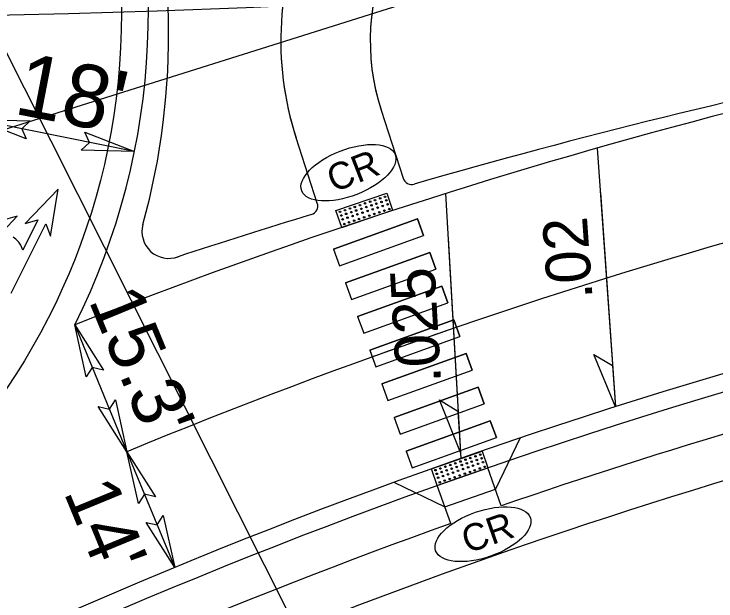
# Model space of a CAD drawing. Extents: x 2010838 to 2015151, y 441905 to 447792.
# Drawn here: x 2013251.3 to 2013329.7, y 444852.7 to 444918.3 of the extents above; entities that cross this region are included whole.
import ezdxf

# ---------------------------------------------------------------- set-up
doc = ezdxf.new("R2010")
doc.units = 0
for name, color, linetype in [('A-Wall-Abov', 7, 'Continuous'), ('A-Wall-Blow', 7, 'Continuous'), ('A-Wall-Comp', 7, 'Continuous'), ('C-CURB STOPS', 7, 'Continuous'), ('C-Grave Plots', 7, 'Continuous'), ('CLRD', 7, 'Continuous'), ('Default_10ft_LIDAR_Contou', 7, 'Continuous'), ('HATCH', 7, 'Continuous'), ('s-Existing Major', 7, 'Continuous'), ('S-Existing Minor', 7, 'Continuous'), ('S-overhead electric', 7, 'Continuous'), ('TEXT-LG', 7, 'Continuous'), ('TEXT-MED', 7, 'Continuous'), ('X4', 7, 'Continuous')]:
    doc.layers.add(name, color=color, linetype=linetype)

msp = doc.modelspace()

# ---------------------------------------------------------------- linework, layer by layer
at = {"layer": 'A-Wall-Abov'}
for points in [[(2013250.956, 444887.056), (2013254.833, 444894.808), (2013255.354, 444893.43), (2013256.211, 444898.684), (2013252.522, 444894.845), (2013253.938, 444895.256), (2013252.251, 444891.882), (2013252.005, 444892.413), (2013251.783, 444892.757), (2013251.453, 444893.1), (2013251.16, 444893.337)], [(2013250.025, 444893.951), (2013251.627, 444895.665), (2013247.938, 444894.622)]]:
    msp.add_lwpolyline(points, dxfattribs=at)
at = {"layer": 'A-Wall-Blow'}
for p, q in [((2013316.475, 444903.287), (2013318.511, 444874.377)), ((2013299.506, 444898.197), (2013301.201, 444868.592))]:
    msp.add_line(p, q, dxfattribs=at)
at = {"layer": 'A-Wall-Comp'}
for p, q in [((2013316.825, 444898.317), (2013318.511, 444874.377)), ((2013299.791, 444893.209), (2013301.164, 444869.248))]:
    msp.add_line(p, q, dxfattribs=at)
for points in [[(2013318.511, 444874.377), (2013316.095, 444880.221), (2013318.186, 444878.99)], [(2013301.164, 444869.248), (2013298.824, 444875.124), (2013300.899, 444873.866)]]:
    msp.add_lwpolyline(points, close=True, dxfattribs=at)
at = {"layer": 'C-CURB STOPS'}
msp.add_line((2013292.307, 444907.526), (2013294.775, 444899.915), dxfattribs=at)
for points in [[(2013282.785, 444904.47), (2013282.785, 444904.47)], [(2013285.169, 444897.119), (2013282.795, 444904.441), (2013282.795, 444904.441), (2013282.785, 444904.47)]]:
    msp.add_lwpolyline(points, dxfattribs=at)
for centre, radius, start, end in [((2013188.546, 444915.993), 80, 344.59886, 17.7968), ((2013316.088, 444915.237), 35, 154.99432, 197.96731), ((2013316.088, 444915.237), 35, 154.99432, 197.9163), ((2013316.088, 444915.237), 25, 154.99432, 197.96731), ((2013316.088, 444915.237), 25, 154.99432, 197.8959), ((2013503.489, 444178.534), 750, 101.653298, 106.060232), ((2013316.088, 444915.237), 25, 197.8959, 197.96731), ((2013295.726, 444900.223), 1, 197.96731, 286.06023), ((2013284.218, 444896.81), 1, 286.97605, 17.96731), ((2013503.489, 444178.534), 750, 106.976046, 108.178762), ((2013268.566, 444893.95), 3, 164.59886, 290.27708)]:
    msp.add_arc(centre, radius, start, end, dxfattribs=at)
at = {"layer": 'CLRD'}
msp.add_arc((2013223.904, 446217.908), 1300, 266.626426, 322.205104, dxfattribs=at)
at = {"layer": 'Default_10ft_LIDAR_Contou'}
msp.add_line((2013248.279, 444918.136), (2013322.298, 444771.201), dxfattribs=at)
at = {"layer": 'HATCH'}
for p, q in [((2013286.971, 444891.987), (2013296.379, 444895.375)), ((2013296.379, 444895.375), (2013286.971, 444891.987)), ((2013296.379, 444895.375), (2013297.057, 444893.494)), ((2013297.057, 444893.494), (2013296.379, 444895.375)), ((2013287.648, 444890.105), (2013297.057, 444893.494)), ((2013287.648, 444890.105), (2013297.057, 444893.494)), ((2013286.971, 444891.987), (2013287.648, 444890.105)), ((2013286.971, 444891.987), (2013287.648, 444890.105)), ((2013288.326, 444888.224), (2013297.734, 444891.612)), ((2013297.734, 444891.612), (2013288.326, 444888.224)), ((2013297.734, 444891.612), (2013298.412, 444889.73)), ((2013298.412, 444889.73), (2013297.734, 444891.612)), ((2013289.004, 444886.342), (2013298.412, 444889.73)), ((2013289.004, 444886.342), (2013298.412, 444889.73)), ((2013288.326, 444888.224), (2013289.004, 444886.342)), ((2013288.326, 444888.224), (2013289.004, 444886.342)), ((2013289.681, 444884.46), (2013299.09, 444887.849)), ((2013299.09, 444887.849), (2013289.681, 444884.46)), ((2013299.09, 444887.849), (2013299.767, 444885.967)), ((2013299.767, 444885.967), (2013299.09, 444887.849)), ((2013290.359, 444882.579), (2013299.767, 444885.967)), ((2013290.359, 444882.579), (2013299.767, 444885.967)), ((2013289.681, 444884.46), (2013290.359, 444882.579)), ((2013289.681, 444884.46), (2013290.359, 444882.579)), ((2013291.036, 444880.697), (2013300.445, 444884.085)), ((2013300.445, 444884.085), (2013291.036, 444880.697)), ((2013300.445, 444884.085), (2013301.123, 444882.203)), ((2013300.745, 444883.251), (2013300.445, 444884.085)), ((2013301.123, 444882.203), (2013300.745, 444883.251)), ((2013291.714, 444878.815), (2013301.123, 444882.203)), ((2013291.714, 444878.815), (2013301.123, 444882.203)), ((2013291.036, 444880.697), (2013291.714, 444878.815)), ((2013291.036, 444880.697), (2013291.311, 444879.936)), ((2013291.311, 444879.936), (2013291.714, 444878.815)), ((2013292.392, 444876.934), (2013301.8, 444880.322)), ((2013301.8, 444880.322), (2013292.392, 444876.934)), ((2013301.8, 444880.322), (2013302.478, 444878.44)), ((2013302.478, 444878.44), (2013301.8, 444880.322)), ((2013293.069, 444875.052), (2013302.478, 444878.44)), ((2013293.069, 444875.052), (2013302.478, 444878.44)), ((2013292.392, 444876.934), (2013293.069, 444875.052)), ((2013292.392, 444876.934), (2013293.069, 444875.052)), ((2013293.747, 444873.17), (2013303.156, 444876.558)), ((2013303.156, 444876.558), (2013293.747, 444873.17)), ((2013303.156, 444876.558), (2013303.833, 444874.677)), ((2013303.833, 444874.677), (2013303.156, 444876.558)), ((2013294.425, 444871.288), (2013303.833, 444874.677)), ((2013294.425, 444871.288), (2013303.833, 444874.677)), ((2013293.747, 444873.17), (2013294.425, 444871.288)), ((2013293.747, 444873.17), (2013294.425, 444871.288)), ((2013295.102, 444869.407), (2013304.511, 444872.795)), ((2013304.511, 444872.795), (2013295.102, 444869.407)), ((2013304.511, 444872.795), (2013305.188, 444870.913)), ((2013305.188, 444870.913), (2013304.511, 444872.795)), ((2013295.78, 444867.525), (2013305.188, 444870.913)), ((2013295.78, 444867.525), (2013305.188, 444870.913)), ((2013295.102, 444869.407), (2013295.78, 444867.525)), ((2013295.102, 444869.407), (2013295.78, 444867.525))]:
    msp.add_line(p, q, dxfattribs=at)
msp.add_circle((2013188.28, 444918.396), 75, dxfattribs=at)
for start, end in [(98.358409, 112.42037), (108.915177, 109.804899), (108.915177, 109.804899)]:
    msp.add_arc((2013509.51, 444274.027), 644, start, end, dxfattribs=at)
at = {"layer": 's-Existing Major'}
for points in [[(2013252.616, 444904.321), (2013247.083, 444906.471), (2013253.055, 444906.322), (2013252.115, 444905.451)], [(2013259.191, 444905.044), (2013264.724, 444902.894), (2013258.752, 444903.044), (2013259.691, 444903.915)], [(2013259.344, 444877.72), (2013258.044, 444883.512), (2013261.249, 444878.471), (2013260.003, 444878.765)], [(2013262.589, 444875.139), (2013263.889, 444869.347), (2013260.684, 444874.389), (2013261.93, 444874.094)], [(2013265.189, 444863.555), (2013263.889, 444869.347), (2013267.094, 444864.306), (2013265.847, 444864.601)], [(2013267.928, 444862.198), (2013269.228, 444856.406), (2013266.023, 444861.447), (2013267.27, 444861.152)]]:
    msp.add_lwpolyline(points, close=True, dxfattribs=at)
at = {"layer": 'S-Existing Minor'}
for p, q in [((2012728.005, 444741.112), (2013407.247, 444954.802)), ((2013264.724, 444902.894), (2013247.083, 444906.471)), ((2013258.044, 444883.512), (2013263.889, 444869.347)), ((2013263.889, 444869.347), (2013269.228, 444856.406))]:
    msp.add_line(p, q, dxfattribs=at)
at = {"layer": 'S-overhead electric'}
for centre, radius, start, end in [((2013188.28, 444918.396), 78, 333.4342, 21.35599), ((2013488.978, 444297.364), 630, 97.858337, 111.50371), ((2013509.51, 444274.027), 630, 98.358409, 116.497126)]:
    msp.add_arc(centre, radius, start, end, dxfattribs=at)
at = {"layer": 'TEXT-LG'}
for p, q in [((2013287.259, 444896.319), (2013292.946, 444898.232)), ((2013292.946, 444898.232), (2013293.583, 444896.336)), ((2013287.896, 444894.423), (2013293.583, 444896.336)), ((2013287.897, 444894.423), (2013287.259, 444896.319)), ((2013307.849, 444870.88), (2013305.08, 444865.149)), ((2013297.93, 444867.436), (2013303.596, 444869.41)), ((2013303.596, 444869.41), (2013304.254, 444867.522)), ((2013298.588, 444865.547), (2013297.93, 444867.436)), ((2013298.588, 444865.547), (2013304.254, 444867.522)), ((2013305.72, 444863.282), (2013304.254, 444867.522)), ((2013293.729, 444865.921), (2013299.415, 444863.174)), ((2013300.1, 444861.309), (2013298.588, 444865.547)), ((2013299.415, 444863.174), (2013305.081, 444865.149))]:
    msp.add_line(p, q, dxfattribs=at)
for centre in [(2013292.742, 444897.836), (2013290.514, 444897.095), (2013291.083, 444897.284), (2013291.628, 444897.465), (2013291.774, 444897.062), (2013292.197, 444897.655), (2013292.344, 444897.251), (2013292.888, 444897.433), (2013288.255, 444896.337), (2013288.824, 444896.527), (2013289.368, 444896.708), (2013289.515, 444896.304), (2013289.938, 444896.898), (2013290.084, 444896.494), (2013290.66, 444896.691), (2013290.801, 444896.253), (2013291.23, 444896.88), (2013291.37, 444896.442), (2013291.915, 444896.624), (2013292.484, 444896.813), (2013292.669, 444896.291), (2013293.029, 444896.995), (2013293.213, 444896.472), (2013287.71, 444896.156), (2013287.857, 444895.752), (2013288.401, 444895.933), (2013288.542, 444895.495), (2013288.97, 444896.123), (2013289.111, 444895.685), (2013289.656, 444895.866), (2013290.225, 444896.056), (2013290.41, 444895.534), (2013290.986, 444895.73), (2013291.555, 444895.92), (2013292.1, 444896.101), (2013287.997, 444895.314), (2013288.182, 444894.792), (2013288.726, 444894.973), (2013289.296, 444895.163), (2013289.84, 444895.344), (2013302.853, 444868.826), (2013303.396, 444869.013), (2013300.602, 444868.044), (2013301.176, 444868.247), (2013301.743, 444868.443), (2013301.894, 444868.04), (2013302.286, 444868.63), (2013302.437, 444868.228), (2013303.004, 444868.423), (2013303.547, 444868.611), (2013303.692, 444868.174), (2013298.383, 444867.278), (2013298.925, 444867.465), (2013299.493, 444867.661), (2013299.644, 444867.258), (2013300.035, 444867.848), (2013300.186, 444867.446), (2013300.753, 444867.642), (2013301.327, 444867.845), (2013301.473, 444867.408), (2013302.04, 444867.604), (2013302.582, 444867.791), (2013302.773, 444867.271), (2013303.15, 444867.987), (2013303.34, 444867.467), (2013303.882, 444867.654), (2013298.534, 444866.875), (2013298.679, 444866.439), (2013299.076, 444867.063), (2013299.222, 444866.626), (2013299.789, 444866.822), (2013300.332, 444867.009), (2013300.522, 444866.489), (2013300.899, 444867.205), (2013301.089, 444866.685), (2013301.663, 444866.888), (2013302.23, 444867.084), (2013298.87, 444865.919), (2013299.412, 444866.106), (2013299.979, 444866.302)]:
    msp.add_circle(centre, 0.0869, dxfattribs=at)
for radius, start, end in [(623.5, 98.358409, 109.077583), (618.5, 101.908184, 116.497126), (623.5, 109.624956, 116.497126), (623.5, 109.624956, 116.497126)]:
    msp.add_arc((2013509.51, 444274.027), radius, start, end, dxfattribs=at)
at = {"layer": 'TEXT-MED'}
msp.add_arc((2013509.51, 444274.027), 628, 98.358409, 116.497126, dxfattribs=at)
at = {"layer": 'X4'}
for centre, major_axis in [((2013288.653, 444900.527), (5.226, 2.032)), ((2013303.696, 444860.12), (5.294, 1.846))]:
    msp.add_ellipse(centre, major_axis=major_axis, ratio=0.462467, dxfattribs=at)

# ---------------------------------------------------------------- texts
at = {"layer": 'A-Wall-Blow'}
for s, rotation, p in [('.02', 94.02794, (2013315.957, 444886.461)), ('.025', 93.27869, (2013299.014, 444877.073))]:
    msp.add_text(s, height=5, rotation=rotation, dxfattribs=at).set_placement(p)
at = {"layer": 'C-Grave Plots'}
for s, height, rotation, p in [("18'", 7, 349.06467, (2013251.102, 444907.153)), ("15.3'", 6, 292.42037, (2013259.562, 444886.266)), ("14'", 6, 292.42037, (2013256.765, 444864.83))]:
    msp.add_text(s, height=height, rotation=rotation, dxfattribs=at).set_placement(p)
at = {"layer": 'X4'}
for rotation, p in [(21.24692, (2013286.992, 444898.296)), (19.22593, (2013301.957, 444857.949))]:
    msp.add_text('CR', height=3, rotation=rotation, dxfattribs=at).set_placement(p)

doc.saveas('drawing.dxf')
